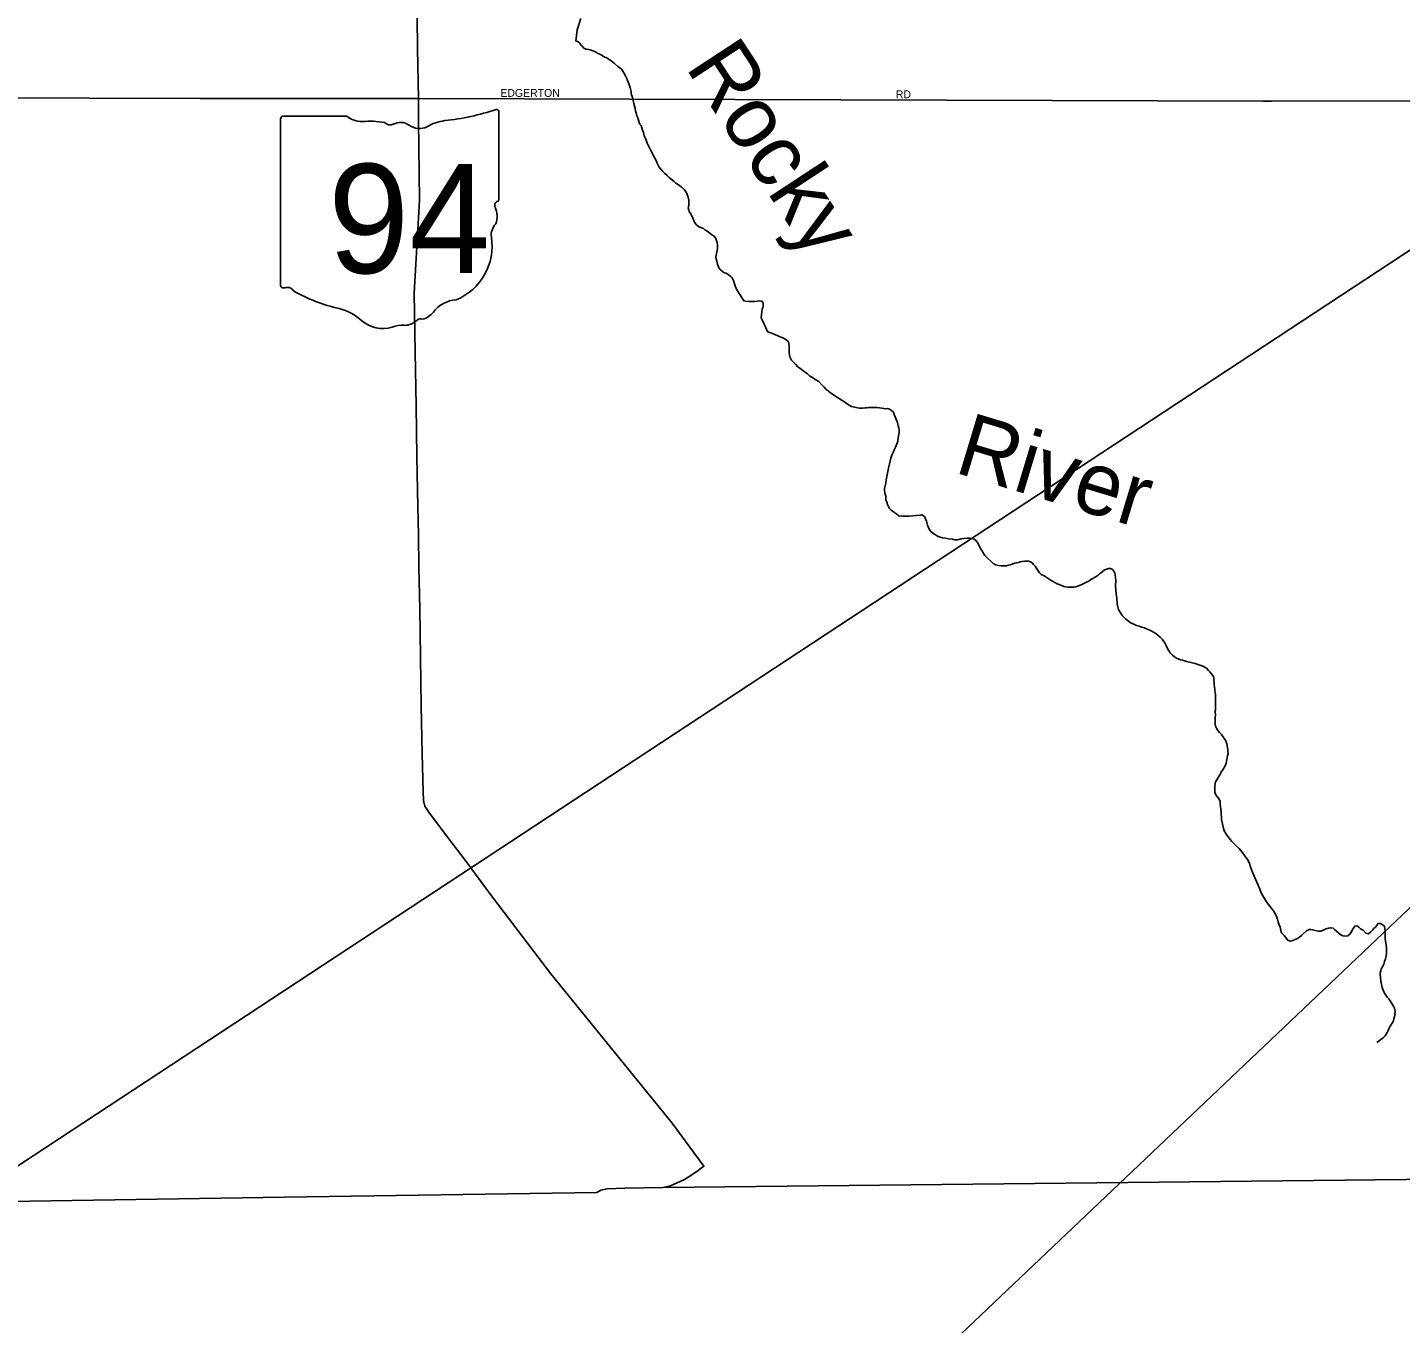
# Model space of a CAD drawing. Extents: x -561 to 1170, y 0 to 846.
# Drawn here: x 214.3 to 237.93, y 67.44 to 89.75 of the extents above; entities that cross this region are included whole.
import ezdxf

# ---------------------------------------------------------------- set-up
doc = ezdxf.new("R2010")
doc.units = 0
for name, color, linetype in [('GM_X_City_Street', 7, 'Continuous'), ('GM_X_City_Street_Text', 7, 'Continuous'), ('GM_X_County', 7, 'Continuous'), ('GM_X_Major_River', 7, 'Continuous'), ('GM_X_Major_River_Text', 7, 'Continuous'), ('GM_X_State_Location', 7, 'Continuous'), ('GM_X_State_Route', 7, 'Continuous'), ('GM_X_State_Shield', 7, 'Continuous'), ('SH_Text', 7, 'Continuous')]:
    doc.layers.add(name, color=color, linetype=linetype)

msp = doc.modelspace()

# ---------------------------------------------------------------- linework, layer by layer
at = {"layer": 'GM_X_City_Street'}
for points in [[(213.437, 88.535), (217.274, 88.525), (221.028, 88.521), (235.566, 88.478), (235.713, 88.479)], [(235.713, 88.479), (241.83, 88.481), (245.819, 88.413), (246.144, 88.403), (246.543, 88.383), (246.924, 88.34), (247.092, 88.274), (247.403, 88.1), (247.756, 87.884), (248.199, 87.567), (248.631, 87.333), (248.966, 87.214), (249.283, 87.154), (249.732, 87.13), (250.199, 87.2), (250.5, 87.281), (251.38, 87.693), (252.234, 88.092), (252.536, 88.194), (252.849, 88.291), (253.495, 88.406), (254.062, 88.405), (254.272, 88.406)]]:
    msp.add_lwpolyline(points, dxfattribs=at)
at = {"layer": 'GM_X_County'}
msp.add_lwpolyline([(282.884, 70.725), (267.704, 70.572), (266.613, 70.549), (250.769, 70.185), (250.464, 70.18), (249.038, 70.146), (242.784, 69.997), (238.571, 69.924), (225.238, 69.779), (224.579, 69.768), (224.275, 69.753), (224.168, 69.735), (224.098, 69.694), (218.724, 69.61), (212.144, 69.507), (206.054, 69.485), (200.736, 69.352), (196.366, 69.25), (195.286, 69.225), (186.974, 69.032)], dxfattribs=at)
at = {"layer": 'GM_X_Major_River'}
for points in [[(224.689, 88.615), (224.688, 88.642), (224.682, 88.669), (224.67, 88.712), (224.658, 88.76), (224.646, 88.793), (224.629, 88.83), (224.611, 88.878), (224.594, 88.911), (224.566, 88.964), (224.549, 88.991), (224.521, 89.028), (224.493, 89.049), (224.46, 89.075), (224.399, 89.133), (224.366, 89.154), (224.338, 89.175), (224.31, 89.196), (224.261, 89.227), (224.228, 89.237), (224.173, 89.274), (224.14, 89.289), (224.112, 89.304), (224.074, 89.325), (224.03, 89.346), (223.986, 89.361), (223.959, 89.365), (223.916, 89.37), (223.877, 89.39), (223.85, 89.417), (223.822, 89.443), (223.81, 89.47), (223.771, 89.502), (223.739, 89.512), (223.771, 89.502), (223.739, 89.512), (223.761, 89.702), (223.826, 89.899)], [(226.959, 84.95), (226.963, 84.977), (226.963, 85.01), (226.935, 85.036), (226.902, 85.041), (226.859, 85.034), (226.81, 85.028), (226.762, 85.026), (226.718, 85.031), (226.664, 85.035), (226.631, 85.039), (226.603, 85.087), (226.519, 85.21), (226.501, 85.242), (226.484, 85.279), (226.467, 85.333), (226.449, 85.392), (226.426, 85.435), (226.404, 85.461), (226.365, 85.488), (226.326, 85.514), (226.299, 85.524), (226.261, 85.544), (226.222, 85.581), (226.199, 85.608), (226.176, 85.672), (226.164, 85.721), (226.152, 85.764), (226.146, 85.791), (226.15, 85.823), (226.16, 85.856), (226.17, 85.905), (226.174, 85.949), (226.178, 85.976), (226.178, 86.009), (226.171, 86.041), (226.159, 86.079), (226.148, 86.116), (226.12, 86.153), (226.081, 86.179), (226.042, 86.206), (225.998, 86.237), (225.96, 86.263), (225.932, 86.284), (225.883, 86.304), (225.85, 86.32), (225.817, 86.346), (225.788, 86.383), (225.777, 86.41), (225.765, 86.437), (225.754, 86.464), (225.719, 86.539), (225.686, 86.576), (225.68, 86.603), (225.673, 86.64), (225.683, 86.679), (225.682, 86.711), (225.681, 86.744), (225.681, 86.771), (225.674, 86.803), (225.668, 86.841), (225.645, 86.9), (225.605, 86.953), (225.55, 87), (225.506, 87.037), (225.461, 87.068), (225.428, 87.095), (225.378, 87.137), (225.345, 87.163), (225.312, 87.2), (225.267, 87.231), (225.234, 87.269), (225.195, 87.311), (225.172, 87.343), (225.138, 87.412), (225.115, 87.466), (225.092, 87.509), (225.041, 87.605), (224.989, 87.707), (224.966, 87.755), (224.943, 87.825), (224.914, 87.878), (224.902, 87.937), (224.885, 87.98), (224.873, 88.018), (224.861, 88.056), (224.838, 88.082), (224.827, 88.109), (224.815, 88.152), (224.803, 88.19), (224.786, 88.222), (224.78, 88.259), (224.767, 88.313), (224.761, 88.351), (224.737, 88.437), (224.731, 88.464), (224.725, 88.491), (224.718, 88.518), (224.707, 88.556), (224.695, 88.588), (224.689, 88.615)], [(229.137, 81.467), (229.114, 81.51), (229.103, 81.537), (229.091, 81.575), (229.074, 81.617), (229.072, 81.677), (229.06, 81.715), (229.054, 81.742), (229.053, 81.774), (229.052, 81.812), (229.062, 81.856), (229.071, 81.899), (229.081, 81.959), (229.118, 82.161), (229.138, 82.232), (229.157, 82.33), (229.177, 82.385), (229.198, 82.429), (229.218, 82.478), (229.244, 82.533), (229.264, 82.577), (229.279, 82.626), (229.283, 82.686), (229.298, 82.74), (229.302, 82.778), (229.301, 82.811), (229.295, 82.854), (229.288, 82.886), (229.282, 82.919), (229.276, 82.946), (229.259, 82.989), (229.247, 83.015), (229.235, 83.042), (229.218, 83.085), (229.206, 83.123), (229.173, 83.154), (229.134, 83.175), (229.102, 83.185), (229.069, 83.184), (229.037, 83.189), (229.004, 83.193), (228.966, 83.198), (228.917, 83.207), (228.868, 83.206), (228.809, 83.204), (228.776, 83.204), (228.749, 83.197), (228.717, 83.197), (228.674, 83.19), (228.614, 83.194), (228.56, 83.203), (228.516, 83.213), (228.483, 83.223), (228.445, 83.244), (228.412, 83.264), (228.362, 83.301), (228.324, 83.327), (228.197, 83.405), (228.158, 83.431), (228.12, 83.457), (228.081, 83.489), (228.048, 83.515), (228.014, 83.552), (227.97, 83.594), (227.92, 83.653), (227.859, 83.689), (227.826, 83.71), (227.798, 83.725), (227.765, 83.746), (227.721, 83.788), (227.671, 83.82), (227.616, 83.862), (227.561, 83.903), (227.516, 83.951), (227.477, 83.993), (227.449, 84.02), (227.432, 84.052), (227.421, 84.079), (227.415, 84.106), (227.408, 84.154), (227.407, 84.187), (227.411, 84.225), (227.41, 84.263), (227.404, 84.306), (227.398, 84.333), (227.353, 84.375), (227.298, 84.401), (227.227, 84.431), (227.161, 84.462), (227.107, 84.482), (227.079, 84.493), (227.041, 84.508), (227.018, 84.545), (227.001, 84.593), (226.972, 84.652), (226.944, 84.711), (226.926, 84.749), (226.94, 84.852), (226.944, 84.896), (226.954, 84.923), (226.959, 84.95)], [(233.017, 80.35), (233.005, 80.382), (232.977, 80.414), (232.939, 80.434), (232.906, 80.433), (232.869, 80.422), (232.831, 80.404), (232.789, 80.371), (232.752, 80.343), (232.725, 80.315), (232.683, 80.292), (232.645, 80.264), (232.603, 80.241), (232.566, 80.213), (232.528, 80.196), (232.491, 80.179), (232.448, 80.156), (232.405, 80.138), (232.373, 80.127), (232.341, 80.12), (232.308, 80.114), (232.254, 80.113), (232.211, 80.112), (232.168, 80.116), (232.135, 80.126), (232.097, 80.141), (232.058, 80.156), (232.025, 80.172), (231.904, 80.239), (231.849, 80.27), (231.8, 80.307), (231.745, 80.332), (231.717, 80.359), (231.695, 80.391), (231.672, 80.428), (231.644, 80.471), (231.616, 80.502), (231.593, 80.529), (231.566, 80.545), (231.528, 80.56), (231.501, 80.559), (231.468, 80.558), (231.42, 80.552), (231.387, 80.545), (231.355, 80.539), (231.323, 80.533), (231.29, 80.526), (231.247, 80.509), (231.215, 80.497), (231.178, 80.491), (231.151, 80.479), (231.102, 80.478), (231.059, 80.477), (231.01, 80.487), (230.961, 80.496), (230.922, 80.522), (230.878, 80.559), (230.828, 80.606), (230.778, 80.659), (230.744, 80.713), (230.715, 80.761), (230.693, 80.803), (230.67, 80.852), (230.653, 80.878), (230.619, 80.921), (230.592, 80.936), (230.553, 80.952), (230.515, 80.956), (230.472, 80.955), (230.413, 80.948), (230.37, 80.941), (230.332, 80.935), (230.305, 80.929), (230.262, 80.928), (230.218, 80.937), (230.153, 80.946), (230.098, 80.956), (230.05, 80.96), (230.011, 80.97), (229.973, 80.985), (229.902, 81.027), (229.846, 81.069), (229.812, 81.122), (229.789, 81.181), (229.771, 81.245), (229.753, 81.299), (229.737, 81.326), (229.692, 81.357), (229.665, 81.351), (229.595, 81.344), (229.536, 81.337), (229.476, 81.335), (229.422, 81.334), (229.368, 81.332), (229.336, 81.337), (229.303, 81.336), (229.264, 81.368), (229.231, 81.389), (229.198, 81.415), (229.165, 81.436), (229.137, 81.467)], [(234.795, 76.834), (234.816, 76.868), (234.831, 76.906), (234.852, 76.939), (234.873, 76.967), (234.889, 76.994), (234.904, 77.022), (234.919, 77.049), (234.929, 77.082), (234.953, 77.207), (234.963, 77.251), (234.962, 77.283), (234.961, 77.316), (234.955, 77.348), (234.948, 77.386), (234.942, 77.418), (234.93, 77.451), (234.919, 77.477), (234.896, 77.509), (234.874, 77.541), (234.851, 77.573), (234.818, 77.61), (234.79, 77.642), (234.767, 77.685), (234.75, 77.722), (234.743, 77.76), (234.742, 77.809), (234.741, 77.863), (234.745, 77.912), (234.743, 77.966), (234.748, 78.004), (234.747, 78.031), (234.746, 78.064), (234.75, 78.107), (234.749, 78.151), (234.748, 78.189), (234.747, 78.227), (234.746, 78.264), (234.74, 78.297), (234.739, 78.324), (234.738, 78.351), (234.732, 78.394), (234.725, 78.432), (234.724, 78.47), (234.718, 78.513), (234.717, 78.546), (234.711, 78.573), (234.671, 78.626), (234.649, 78.652), (234.627, 78.679), (234.593, 78.716), (234.543, 78.747), (234.5, 78.762), (234.461, 78.777), (234.396, 78.797), (234.325, 78.817), (234.298, 78.822), (234.249, 78.831), (234.216, 78.841), (234.178, 78.857), (234.145, 78.861), (234.118, 78.871), (234.079, 78.892), (234.041, 78.913), (234.008, 78.939), (233.969, 78.981), (233.94, 79.029), (233.912, 79.077), (233.9, 79.11), (233.883, 79.142), (233.86, 79.179), (233.827, 79.216), (233.793, 79.253), (233.755, 79.285), (233.721, 79.316), (233.683, 79.337), (233.639, 79.363), (233.59, 79.383), (233.562, 79.394), (233.524, 79.409), (233.48, 79.424), (233.431, 79.439), (233.387, 79.454), (233.344, 79.474), (233.294, 79.495), (233.206, 79.563), (233.173, 79.589), (233.145, 79.621), (233.122, 79.653), (233.1, 79.685), (233.077, 79.728), (233.065, 79.771), (233.053, 79.825), (233.05, 79.928), (233.037, 79.998), (233.03, 80.063), (233.028, 80.144), (233.031, 80.22), (233.024, 80.279), (233.023, 80.323), (233.017, 80.35)], [(237.501, 74.26), (237.475, 74.238), (237.449, 74.21), (237.422, 74.177), (237.38, 74.143), (237.336, 74.158), (237.292, 74.206), (237.242, 74.232), (237.215, 74.258), (237.181, 74.284), (237.144, 74.278), (237.123, 74.245), (237.107, 74.217), (237.087, 74.179), (237.061, 74.14), (237.024, 74.112), (236.98, 74.105), (236.942, 74.11), (236.904, 74.125), (236.871, 74.157), (236.832, 74.188), (236.804, 74.215), (236.771, 74.241), (236.728, 74.25), (236.69, 74.244), (236.652, 74.232), (236.561, 74.192), (236.513, 74.191), (236.464, 74.2), (236.42, 74.215), (236.387, 74.22), (236.36, 74.219), (236.312, 74.196), (236.265, 74.152), (236.233, 74.124), (236.196, 74.09), (236.159, 74.062), (236.121, 74.045), (236.089, 74.033), (236.062, 74.022), (236.035, 74.021), (235.992, 74.036), (235.963, 74.073), (235.935, 74.11), (235.908, 74.137), (235.885, 74.163), (235.873, 74.201), (235.861, 74.26), (235.838, 74.314), (235.826, 74.351), (235.814, 74.4), (235.802, 74.427), (235.785, 74.47), (235.768, 74.502), (235.745, 74.539), (235.717, 74.576), (235.689, 74.614), (235.639, 74.677), (235.599, 74.741), (235.565, 74.8), (235.536, 74.853), (235.513, 74.913), (235.484, 74.982), (235.415, 75.138), (235.386, 75.207), (235.357, 75.282), (235.327, 75.374), (235.299, 75.422), (235.282, 75.449), (235.248, 75.496), (235.209, 75.55), (235.153, 75.613), (235.086, 75.677), (235.025, 75.74), (234.958, 75.82), (234.924, 75.873), (234.896, 75.915), (234.884, 75.959), (234.872, 76.007), (234.865, 76.061), (234.853, 76.11), (234.851, 76.158), (234.845, 76.201), (234.844, 76.25), (234.837, 76.293), (234.836, 76.337), (234.83, 76.364), (234.829, 76.396), (234.828, 76.423), (234.817, 76.45), (234.799, 76.482), (234.766, 76.519), (234.749, 76.546), (234.737, 76.578), (234.736, 76.621), (234.735, 76.659), (234.734, 76.692), (234.744, 76.73), (234.749, 76.763), (234.769, 76.796), (234.795, 76.834)], [(237.525, 72.273), (237.639, 72.361), (237.666, 72.389), (237.687, 72.416), (237.702, 72.444), (237.717, 72.482), (237.733, 72.51), (237.748, 72.543), (237.81, 72.647), (237.82, 72.685), (237.83, 72.718), (237.835, 72.745), (237.834, 72.772), (237.838, 72.805), (237.832, 72.837), (237.826, 72.864), (237.815, 72.891), (237.781, 72.945), (237.752, 72.993), (237.73, 73.025), (237.707, 73.051), (237.668, 73.104), (237.639, 73.158), (237.616, 73.222), (237.598, 73.303), (237.585, 73.384), (237.582, 73.465), (237.592, 73.509), (237.602, 73.542), (237.623, 73.575), (237.643, 73.624), (237.658, 73.668), (237.673, 73.712), (237.683, 73.761), (237.692, 73.81), (237.691, 73.858), (237.69, 73.907), (237.677, 73.988), (237.669, 74.053), (237.668, 74.107), (237.667, 74.156), (237.666, 74.188), (237.665, 74.232), (237.658, 74.275), (237.619, 74.307), (237.581, 74.322), (237.543, 74.321), (237.522, 74.288), (237.501, 74.26)]]:
    msp.add_lwpolyline(points, dxfattribs=at)
at = {"layer": 'GM_X_State_Route'}
for points in [[(221.032, 88.15), (221.028, 88.521), (221.014, 89.379), (220.969, 93.728), (220.826, 95.632), (220.813, 96.85), (220.801, 98.095), (220.778, 99.248), (220.771, 100.59), (220.748, 102.008), (220.725, 103.193), (220.702, 104.714), (220.816, 105.174), (220.791, 106.155), (220.634, 113.482)], [(225.874, 70.094), (225.942, 70.145), (225.394, 70.888), (223.306, 73.456), (222.813, 74.105), (222.288, 74.798), (221.834, 75.415), (221.46, 75.902), (221.205, 76.237), (221.14, 76.34), (221.113, 76.438), (221.108, 76.595), (221.091, 77.244), (221.074, 78.062), (221.062, 78.911), (221.051, 79.745), (221.034, 80.454), (221.028, 81.006), (221.017, 81.499), (221, 82.354), (220.988, 83.237), (220.971, 84.157), (220.954, 85.175), (221.046, 86.767), (221.032, 88.15)], [(225.238, 69.779), (225.369, 69.81), (225.606, 69.919), (225.733, 69.996), (225.844, 70.072), (225.874, 70.094)]]:
    msp.add_lwpolyline(points, dxfattribs=at)
at = {"layer": 'GM_X_State_Shield'}
for p, q in [((218.655, 88.168), (218.655, 85.315)), ((219.793, 88.217), (218.692, 88.217)), ((222.414, 86.796), (222.414, 88.288)), ((222.414, 86.796), (222.414, 86.796))]:
    msp.add_line(p, q, dxfattribs=at)
for centre, radius, start, end in [((218.699, 88.174), 0.0435, 98.1301, 188.1301), ((220.055, 88.549), 0.422, 231.6195, 271.1119), ((221.075, 92.107), 3.986, 275.8445, 288.9065), ((222.373, 88.294), 0.0418, 351.8621, 97.738), ((220.195, 86.616), 1.516, 80.4867, 94.9883), ((220.54, 88.189), 0.122, 219.7921, 297.1024), ((220.719, 87.859), 0.253, 54.4667, 119.1411), ((221.046, 88.312), 0.305, 233.8562, 294.8282), ((221.584, 87.346), 0.802, 97.3462, 120.7689), ((222.405, 86.686), 0.0648, 107.944, 210.337), ((222.37, 86.79), 0.0448, 289.6038, 7.7341), ((221.993, 86.498), 0.389, 340.033, 23.6496), ((222.564, 86.171), 0.283, 136.8065, 186.9296), ((221.299, 85.981), 0.997, 292.3089, 8.9858), ((218.699, 85.309), 0.0439, 171.9584, 258.3066), ((218.706, 85.601), 0.335, 267.339, 280.6039), ((218.774, 85.151), 0.121, 29.7484, 93.2717), ((220.3, 87.714), 2.879, 240.4129, 257.1985), ((219.442, 84.034), 0.901, 47.1842, 75.836), ((221.719, 84.514), 0.546, 94.4031, 142.5768), ((220.416, 85.137), 0.572, 230.7004, 286.2918), ((220.747, 84.15), 0.47, 85.6951, 111.2099), ((220.788, 84.923), 0.305, 268.777, 315.5493), ((221.064, 84.647), 0.0857, 65.7517, 132.6484), ((221.027, 85.039), 0.322, 282.8732, 323.2771)]:
    msp.add_arc(centre, radius, start, end, dxfattribs=at)
at = {"layer": 'SH_Text'}
msp.add_lwpolyline([(203.796, 63.354), (276.905, 111.448), (203.796, 42.031)], close=True, dxfattribs=at)

# ---------------------------------------------------------------- texts
at = {"layer": 'GM_X_City_Street_Text'}
for s, p in [('EDGERTON', (222.438, 88.551)), ('RD', (229.245, 88.527))]:
    msp.add_text(s, height=0.135, rotation=0, dxfattribs=at).set_placement(p)
at = {"layer": 'GM_X_Major_River_Text'}
for s, rotation, p in [('Rocky', 303.2545, (225.611, 89.067)), ('River', 343.1711, (230.229, 82.094))]:
    msp.add_text(s, height=1.0806, rotation=rotation, dxfattribs=at).set_placement(p)
at = {"layer": 'GM_X_State_Location'}
for s in ['s', 'r']:
    msp.add_text(s, height=0.0027, dxfattribs=at).set_placement((220.492, 86.552))
msp.add_text('94', height=0.0027, rotation=0, dxfattribs=at).set_placement((219.813, 86.356))
at = {"layer": 'GM_X_State_Shield'}
msp.add_text('94', height=1.8795, dxfattribs=at).set_placement((219.472, 85.517))

doc.saveas('drawing.dxf')
